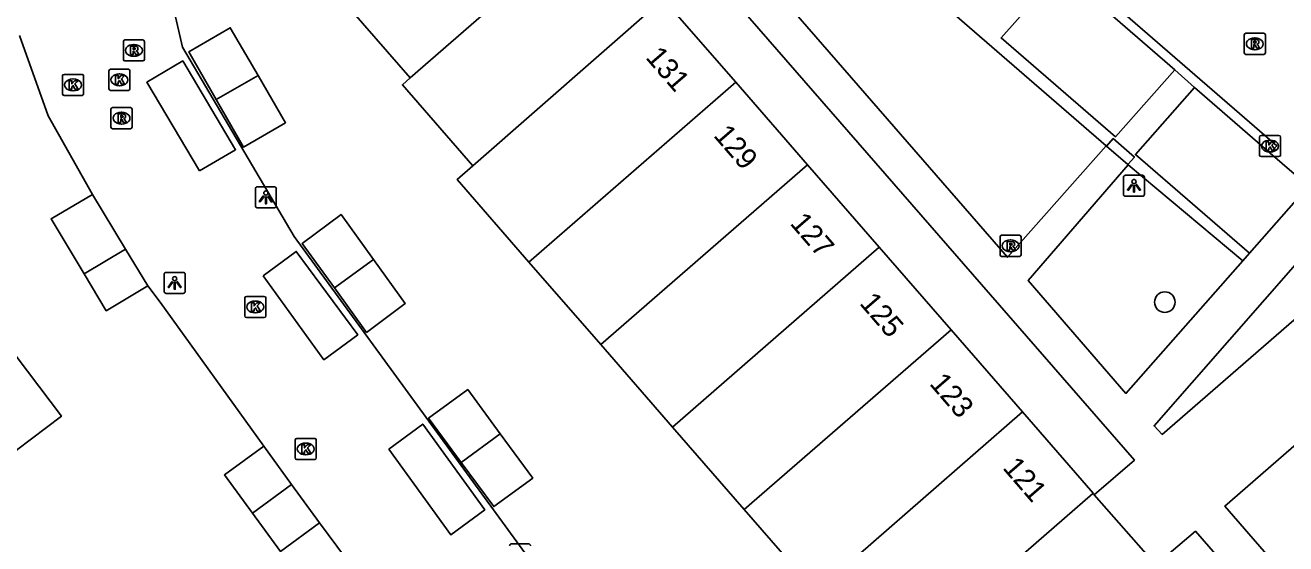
# Model space of a CAD drawing. Extents: x 161882 to 162509, y 381687 to 382379.
# Drawn here: x 161977.5 to 162037.4, y 382136.1 to 382160.8 of the extents above; entities that cross this region are included whole.
import ezdxf

# ---------------------------------------------------------------- set-up
doc = ezdxf.new("R2010")
doc.units = 0
for name, color, linetype in [('IMGEO_Boom', 7, 'Continuous'), ('IMGEO_Kolk', 7, 'Continuous'), ('IMGEO_Lichtpunt', 7, 'Continuous'), ('IMGEO_Pand', 7, 'Continuous'), ('IMGEO_Pand_nummerreeks', 7, 'Continuous'), ('IMGEO_Rijbaan_lokaal_open', 7, 'Continuous'), ('IMGEO_Rioolput', 7, 'Continuous'), ('IMGEO_Voetpad_open', 7, 'Continuous')]:
    doc.layers.add(name, color=color, linetype=linetype)

msp = doc.modelspace()

# ---------------------------------------------------------------- linework, layer by layer
at = {"layer": 'IMGEO_Boom'}
msp.add_circle((162031.641, 382147.613), 0.489, dxfattribs=at)
at = {"layer": 'IMGEO_Kolk'}
for p, q in [((161981.575, 382158.667), (161982.427, 382158.667)), ((161979.297, 382157.502), (161979.297, 382158.354)), ((161979.372, 382158.428), (161980.224, 382158.428)), ((161979.785, 382158.208), (161979.81, 382158.208)), ((161980.298, 382158.354), (161980.298, 382157.502)), ((161981.5, 382157.741), (161981.5, 382158.593)), ((161981.988, 382158.447), (161982.013, 382158.447)), ((161982.501, 382158.593), (161982.501, 382157.741)), ((161980.224, 382157.428), (161979.372, 382157.428)), ((161979.808, 382157.648), (161979.783, 382157.648)), ((161982.427, 382157.667), (161981.575, 382157.667)), ((161982.011, 382157.887), (161981.986, 382157.887)), ((162036.135, 382154.598), (162036.135, 382155.45)), ((162036.21, 382155.524), (162037.062, 382155.524)), ((162036.623, 382155.304), (162036.648, 382155.304)), ((162037.136, 382155.45), (162037.136, 382154.598)), ((162037.062, 382154.524), (162036.21, 382154.524)), ((162036.646, 382154.744), (162036.621, 382154.744)), ((161988.027, 382147.885), (161988.879, 382147.885)), ((161987.952, 382146.959), (161987.952, 382147.811)), ((161988.44, 382147.665), (161988.465, 382147.665)), ((161988.953, 382147.811), (161988.953, 382146.959)), ((161988.879, 382146.885), (161988.027, 382146.885)), ((161988.463, 382147.105), (161988.438, 382147.105)), ((161990.347, 382140.216), (161990.347, 382141.068)), ((161990.422, 382141.142), (161991.274, 382141.142)), ((161990.835, 382140.922), (161990.86, 382140.922)), ((161991.348, 382141.068), (161991.348, 382140.216)), ((161991.274, 382140.142), (161990.422, 382140.142)), ((161990.858, 382140.362), (161990.833, 382140.362))]:
    msp.add_line(p, q, dxfattribs=at)
for points in [[(161981.575, 382158.667), (161982.427, 382158.667)], [(161979.297, 382157.502), (161979.297, 382158.354)], [(161979.372, 382158.428), (161980.224, 382158.428)], [(161979.618, 382158.128), (161979.741, 382158.128), (161979.741, 382157.977), (161979.871, 382158.128), (161980.035, 382158.128), (161979.889, 382157.977), (161980.042, 382157.728), (161979.89, 382157.728), (161979.805, 382157.892), (161979.741, 382157.825), (161979.741, 382157.728), (161979.618, 382157.728), (161979.618, 382158.128)], [(161980.298, 382158.354), (161980.298, 382157.502)], [(161981.5, 382157.741), (161981.5, 382158.593)], [(161981.821, 382158.367), (161981.944, 382158.367), (161981.944, 382158.216), (161982.074, 382158.367), (161982.238, 382158.367), (161982.092, 382158.216), (161982.245, 382157.967), (161982.093, 382157.967), (161982.008, 382158.131), (161981.944, 382158.064), (161981.944, 382157.967), (161981.821, 382157.967), (161981.821, 382158.367)], [(161982.501, 382158.593), (161982.501, 382157.741)], [(161980.224, 382157.428), (161979.372, 382157.428)], [(161982.427, 382157.667), (161981.575, 382157.667)], [(162036.135, 382154.598), (162036.135, 382155.45)], [(162036.21, 382155.524), (162037.062, 382155.524)], [(162036.456, 382155.224), (162036.579, 382155.224), (162036.579, 382155.073), (162036.709, 382155.224), (162036.873, 382155.224), (162036.727, 382155.073), (162036.88, 382154.824), (162036.728, 382154.824), (162036.643, 382154.988), (162036.579, 382154.921), (162036.579, 382154.824), (162036.456, 382154.824), (162036.456, 382155.224)], [(162037.136, 382155.45), (162037.136, 382154.598)], [(162037.062, 382154.524), (162036.21, 382154.524)], [(161988.027, 382147.885), (161988.879, 382147.885)], [(161987.952, 382146.959), (161987.952, 382147.811)], [(161988.273, 382147.585), (161988.396, 382147.585), (161988.396, 382147.434), (161988.526, 382147.585), (161988.69, 382147.585), (161988.544, 382147.434), (161988.697, 382147.185), (161988.545, 382147.185), (161988.46, 382147.349), (161988.396, 382147.282), (161988.396, 382147.185), (161988.273, 382147.185), (161988.273, 382147.585)], [(161988.953, 382147.811), (161988.953, 382146.959)], [(161988.879, 382146.885), (161988.027, 382146.885)], [(161990.347, 382140.216), (161990.347, 382141.068)], [(161990.422, 382141.142), (161991.274, 382141.142)], [(161990.668, 382140.842), (161990.791, 382140.842), (161990.791, 382140.691), (161990.921, 382140.842), (161991.085, 382140.842), (161990.939, 382140.691), (161991.092, 382140.442), (161990.94, 382140.442), (161990.855, 382140.606), (161990.791, 382140.539), (161990.791, 382140.442), (161990.668, 382140.442), (161990.668, 382140.842)], [(161991.348, 382141.068), (161991.348, 382140.216)], [(161991.274, 382140.142), (161990.422, 382140.142)]]:
    msp.add_lwpolyline(points, dxfattribs=at)
for centre, start, end in [((161981.577, 382158.591), 91.55205, 178.44795), ((161981.577, 382158.591), 91.55205, 178.44795), ((161982.425, 382158.591), 1.55205, 88.44795), ((161982.425, 382158.591), 1.55205, 88.44795), ((161979.374, 382158.352), 91.55205, 178.44795), ((161979.374, 382158.352), 91.55205, 178.44795), ((161980.222, 382158.352), 1.55205, 88.44795), ((161980.222, 382158.352), 1.55205, 88.44795), ((161979.374, 382157.504), 181.55205, 268.44795), ((161979.374, 382157.504), 181.55205, 268.44795), ((161980.222, 382157.504), 271.55205, 358.44795), ((161980.222, 382157.504), 271.55205, 358.44795), ((161981.577, 382157.743), 181.55205, 268.44795), ((161981.577, 382157.743), 181.55205, 268.44795), ((161982.425, 382157.743), 271.55205, 358.44795), ((161982.425, 382157.743), 271.55205, 358.44795), ((162036.212, 382155.448), 91.55205, 178.44795), ((162036.212, 382155.448), 91.55205, 178.44795), ((162037.06, 382155.448), 1.55205, 88.44795), ((162037.06, 382155.448), 1.55205, 88.44795), ((162036.212, 382154.6), 181.55205, 268.44795), ((162036.212, 382154.6), 181.55205, 268.44795), ((162037.06, 382154.6), 271.55205, 358.44795), ((162037.06, 382154.6), 271.55205, 358.44795), ((161988.029, 382147.809), 91.55205, 178.44795), ((161988.029, 382147.809), 91.55205, 178.44795), ((161988.877, 382147.809), 1.55205, 88.44795), ((161988.877, 382147.809), 1.55205, 88.44795), ((161988.029, 382146.961), 181.55205, 268.44795), ((161988.029, 382146.961), 181.55205, 268.44795), ((161988.877, 382146.961), 271.55205, 358.44795), ((161988.877, 382146.961), 271.55205, 358.44795), ((161990.424, 382141.066), 91.55205, 178.44795), ((161990.424, 382141.066), 91.55205, 178.44795), ((161991.272, 382141.066), 1.55205, 88.44795), ((161991.272, 382141.066), 1.55205, 88.44795), ((161990.424, 382140.218), 181.55205, 268.44795), ((161990.424, 382140.218), 181.55205, 268.44795), ((161991.272, 382140.218), 271.55205, 358.44795), ((161991.272, 382140.218), 271.55205, 358.44795)]:
    msp.add_arc(centre, 0.0765, start, end, dxfattribs=at)
for centre, major_axis, ratio, start_param, end_param in [((161979.784, 382157.928), (-0.387, 0.002), 0.722429, 4.712389, 7.853982), ((161979.809, 382157.928), (-0.39, 0.002), 0.717154, 1.570796, 4.712389), ((161981.987, 382158.167), (-0.387, 0.002), 0.722429, 4.712389, 7.853982), ((161982.012, 382158.167), (-0.39, 0.002), 0.717154, 1.570796, 4.712389), ((162036.622, 382155.024), (-0.387, 0.002), 0.722429, 4.712389, 7.853982), ((162036.647, 382155.024), (-0.39, 0.002), 0.717154, 1.570796, 4.712389), ((161988.439, 382147.385), (-0.387, 0.002), 0.722429, 4.712389, 7.853982), ((161988.464, 382147.385), (-0.39, 0.002), 0.717154, 1.570796, 4.712389), ((161990.834, 382140.642), (-0.387, 0.002), 0.722429, 4.712389, 7.853982), ((161990.859, 382140.642), (-0.39, 0.002), 0.717154, 1.570796, 4.712389)]:
    msp.add_ellipse(centre, major_axis=major_axis, ratio=ratio, start_param=start_param, end_param=end_param, dxfattribs=at)
at = {"layer": 'IMGEO_Lichtpunt'}
for p, q in [((162029.678, 382153.541), (162029.678, 382152.734)), ((162029.678, 382153.541), (162029.678, 382152.734)), ((162030.58, 382153.636), (162029.772, 382153.636)), ((162030.58, 382153.636), (162029.772, 382153.636)), ((162030.674, 382152.734), (162030.674, 382153.541)), ((162030.674, 382152.734), (162030.674, 382153.541)), ((161988.455, 382152.994), (161988.455, 382152.187)), ((161988.455, 382152.994), (161988.455, 382152.187)), ((161989.357, 382153.089), (161988.549, 382153.089)), ((161989.357, 382153.089), (161988.549, 382153.089)), ((161989.451, 382152.187), (161989.451, 382152.994)), ((161989.451, 382152.187), (161989.451, 382152.994)), ((162029.772, 382152.64), (162030.58, 382152.64)), ((162029.772, 382152.64), (162030.58, 382152.64)), ((161988.549, 382152.093), (161989.357, 382152.093)), ((161988.549, 382152.093), (161989.357, 382152.093)), ((161984.126, 382148.93), (161984.126, 382148.123)), ((161984.126, 382148.93), (161984.126, 382148.123)), ((161985.028, 382149.025), (161984.22, 382149.025)), ((161985.028, 382149.025), (161984.22, 382149.025)), ((161985.122, 382148.123), (161985.122, 382148.93)), ((161985.122, 382148.123), (161985.122, 382148.93)), ((161984.22, 382148.029), (161985.028, 382148.029)), ((161984.22, 382148.029), (161985.028, 382148.029)), ((162001.427, 382136.14), (162000.619, 382136.14)), ((162001.427, 382136.14), (162000.619, 382136.14))]:
    msp.add_line(p, q, dxfattribs=at)
for points in [[(161988.829, 382152.658), (161988.868, 382152.63), (161988.68, 382152.368), (161988.642, 382152.395), (161988.829, 382152.658)], [(161989.041, 382152.63), (161989.079, 382152.657), (161989.266, 382152.395), (161989.227, 382152.367), (161989.041, 382152.63)], [(162030.052, 382153.205), (162030.091, 382153.177), (162029.903, 382152.915), (162029.865, 382152.942), (162030.052, 382153.205)], [(162030.154, 382153.157), (162030.201, 382153.157), (162030.201, 382152.835), (162030.154, 382152.835), (162030.154, 382153.157)], [(162030.264, 382153.177), (162030.302, 382153.204), (162030.489, 382152.942), (162030.45, 382152.914), (162030.264, 382153.177)], [(161988.931, 382152.61), (161988.978, 382152.61), (161988.978, 382152.288), (161988.931, 382152.288), (161988.931, 382152.61)], [(161984.5, 382148.594), (161984.539, 382148.566), (161984.351, 382148.304), (161984.313, 382148.331), (161984.5, 382148.594)], [(161984.602, 382148.546), (161984.649, 382148.546), (161984.649, 382148.224), (161984.602, 382148.224), (161984.602, 382148.546)], [(161984.712, 382148.566), (161984.75, 382148.593), (161984.937, 382148.331), (161984.898, 382148.303), (161984.712, 382148.566)]]:
    msp.add_lwpolyline(points, dxfattribs=at)
for centre in [(162030.177, 382153.339), (161988.954, 382152.792), (161984.625, 382148.728)]:
    msp.add_circle(centre, 0.0994, dxfattribs=at)
for centre, start, end in [((162029.772, 382153.541), 90, 180), ((162029.772, 382153.541), 90, 180), ((162030.58, 382153.541), 0, 90), ((162030.58, 382153.541), 0, 90), ((161988.549, 382152.994), 90, 180), ((161988.549, 382152.994), 90, 180), ((161989.357, 382152.994), 0, 90), ((161989.357, 382152.994), 0, 90), ((162029.772, 382152.734), 180, 270), ((162029.772, 382152.734), 180, 270), ((162030.58, 382152.734), 270, 0), ((162030.58, 382152.734), 270, 360), ((161988.549, 382152.187), 180, 270), ((161988.549, 382152.187), 180, 270), ((161989.357, 382152.187), 270, 0), ((161989.357, 382152.187), 270, 360), ((161984.22, 382148.93), 90, 180), ((161984.22, 382148.93), 90, 180), ((161985.028, 382148.93), 0, 90), ((161985.028, 382148.93), 0, 90), ((161984.22, 382148.123), 180, 270), ((161984.22, 382148.123), 180, 270), ((161985.028, 382148.123), 270, 0), ((161985.028, 382148.123), 270, 360), ((162000.619, 382136.045), 90, 180), ((162000.619, 382136.045), 90, 180), ((162001.427, 382136.045), 0, 90), ((162001.427, 382136.045), 0, 90)]:
    msp.add_arc(centre, 0.0946, start, end, dxfattribs=at)
at = {"layer": 'IMGEO_Pand'}
for points in [[(161995.812, 382158.259), (162004.5, 382165.829)], [(161995.812, 382158.259), (161992.464, 382162.114), (161993.025, 382162.6)], [(162007.819, 382162.014), (161998.778, 382154.082)], [(162007.819, 382162.014), (162011.263, 382158.057)], [(161986.59, 382157.233), (161985.29, 382159.491), (161987.263, 382160.644), (161988.581, 382158.38)], [(161988.581, 382158.38), (161989.893, 382156.127), (161987.89, 382154.975), (161986.59, 382157.233)], [(161986.59, 382157.233), (161988.581, 382158.38)], [(161998.778, 382154.082), (161995.439, 382157.934), (161995.812, 382158.259)], [(162011.263, 382158.057), (162001.445, 382149.514)], [(162011.263, 382158.057), (162014.672, 382154.139)], [(162001.445, 382149.514), (161998.036, 382153.431), (161998.778, 382154.082)], [(162004.853, 382145.596), (162014.672, 382154.139)], [(162014.672, 382154.139), (162018.08, 382150.222)], [(161980.324, 382148.955), (161978.753, 382151.575), (161980.726, 382152.72)], [(161980.726, 382152.72), (161982.291, 382150.133)], [(161992.21, 382148.289), (161990.682, 382150.401), (161992.528, 382151.781), (161994.072, 382149.636)], [(161982.291, 382150.133), (161980.324, 382148.955)], [(161982.291, 382150.133), (161983.351, 382148.38)], [(161994.072, 382149.636), (161995.572, 382147.554), (161993.738, 382146.177), (161992.21, 382148.289)], [(161992.21, 382148.289), (161994.072, 382149.636)], [(162018.08, 382150.222), (162008.262, 382141.679)], [(162018.08, 382150.222), (162021.489, 382146.305)], [(162004.853, 382145.596), (162001.445, 382149.514)], [(161983.351, 382148.38), (161981.375, 382147.201), (161980.324, 382148.955)], [(162021.489, 382146.305), (162011.67, 382137.761)], [(162021.489, 382146.305), (162024.884, 382142.404)], [(162008.262, 382141.679), (162004.853, 382145.596)], [(161965.061, 382130.908), (161972.501, 382136.553), (161972.827, 382136.122), (161974.839, 382137.64), (161974.538, 382138.04), (161976.878, 382139.805), (161977.107, 382140.581), (161979.246, 382142.194), (161977.09, 382145.052), (161970.383, 382139.994)], [(161998.232, 382140.005), (161996.684, 382142.103), (161998.537, 382143.459), (162000.079, 382141.367)], [(162024.884, 382142.404), (162015.457, 382134.174)], [(162024.884, 382142.404), (162028.242, 382138.545), (162028.227, 382138.532)], [(162000.079, 382141.367), (162001.631, 382139.261), (161999.779, 382137.907), (161998.232, 382140.005)], [(161998.232, 382140.005), (162000.079, 382141.367)], [(162011.67, 382137.761), (162008.262, 382141.679)], [(161988.317, 382137.593), (161986.986, 382139.41), (161988.85, 382140.776)], [(161988.85, 382140.776), (161990.178, 382138.957)], [(161990.178, 382138.957), (161988.317, 382137.593)], [(161990.178, 382138.957), (161991.508, 382137.137)], [(162018.798, 382130.333), (162028.227, 382138.532)], [(162015.457, 382134.174), (162015.079, 382133.844), (162011.67, 382137.761)], [(161991.508, 382137.137), (161989.649, 382135.775), (161988.317, 382137.593)]]:
    msp.add_lwpolyline(points, dxfattribs=at)
at = {"layer": 'IMGEO_Rijbaan_lokaal_open'}
for points in [[(162036.646, 382154.691), (162036.967, 382155.028), (162001.899, 382185.403), (162000.705, 382186.422), (162000.438, 382186.65), (162000.135, 382186.301)], [(162010.46, 382123.082), (161990.302, 382150.73), (161984.998, 382159.715), (161980.188, 382180.574), (161980.177, 382180.625)], [(162026.682, 382163.354), (162032.109, 382158.646)], [(161977.25, 382160.268), (161978.622, 382156.462), (161980.726, 382152.72)], [(161985.8, 382153.843), (161983.301, 382158.05), (161985.004, 382159.062), (161987.518, 382154.845), (161985.8, 382153.843)], [(162033.054, 382157.803), (162032.109, 382158.646)], [(162033.054, 382157.803), (162036.646, 382154.691)], [(162036.646, 382154.691), (162038.456, 382153.122)], [(161988.825, 382148.858), (161990.399, 382150.018), (161993.32, 382146.068), (161991.708, 382144.88), (161988.825, 382148.858)], [(161983.351, 382148.38), (161983.941, 382147.611), (161988.85, 382140.776)], [(161994.801, 382140.635), (161996.401, 382141.827), (161999.349, 382137.746), (161997.743, 382136.564), (161994.801, 382140.635)], [(161991.508, 382137.137), (161995.614, 382131.603)]]:
    msp.add_lwpolyline(points, dxfattribs=at)
at = {"layer": 'IMGEO_Rioolput'}
for p, q in [((161982.187, 382159.138), (161982.187, 382159.99)), ((161982.262, 382160.064), (161983.114, 382160.064)), ((161982.675, 382159.844), (161982.7, 382159.844)), ((161983.188, 382159.99), (161983.188, 382159.138)), ((162035.413, 382159.452), (162035.413, 382160.304)), ((162035.488, 382160.378), (162036.34, 382160.378)), ((162035.901, 382160.158), (162035.926, 382160.158)), ((162036.414, 382160.304), (162036.414, 382159.452)), ((161982.698, 382159.284), (161982.673, 382159.284)), ((162036.34, 382159.378), (162035.488, 382159.378)), ((162035.924, 382159.598), (162035.899, 382159.598)), ((161983.114, 382159.064), (161982.262, 382159.064)), ((161981.675, 382156.848), (161982.527, 382156.848)), ((161981.6, 382155.922), (161981.6, 382156.774)), ((161982.088, 382156.628), (161982.113, 382156.628)), ((161982.601, 382156.774), (161982.601, 382155.922)), ((161982.527, 382155.848), (161981.675, 382155.848)), ((161982.111, 382156.068), (161982.086, 382156.068)), ((162023.815, 382149.86), (162023.815, 382150.712)), ((162023.89, 382150.786), (162024.742, 382150.786)), ((162024.303, 382150.566), (162024.328, 382150.566)), ((162024.816, 382150.712), (162024.816, 382149.86)), ((162024.742, 382149.786), (162023.89, 382149.786)), ((162024.326, 382150.006), (162024.301, 382150.006))]:
    msp.add_line(p, q, dxfattribs=at)
for points in [[(161982.187, 382159.138), (161982.187, 382159.99)], [(161982.262, 382160.064), (161983.114, 382160.064)], [(161983.188, 382159.99), (161983.188, 382159.138)], [(162035.413, 382159.452), (162035.413, 382160.304)], [(162035.488, 382160.378), (162036.34, 382160.378)], [(162036.002, 382160.076), (162035.75, 382160.078), (162035.75, 382159.678)], [(162035.75, 382159.678), (162035.874, 382159.678), (162035.874, 382159.84), (162035.885, 382159.84)], [(162035.928, 382159.997), (162035.874, 382159.997), (162035.874, 382159.916)], [(162035.874, 382159.916), (162035.926, 382159.916)], [(162035.932, 382159.811), (162036.003, 382159.678), (162036.143, 382159.678), (162036.078, 382159.804)], [(162036.414, 382160.304), (162036.414, 382159.452)], [(161982.776, 382159.762), (161982.524, 382159.764), (161982.524, 382159.364)], [(161982.524, 382159.364), (161982.648, 382159.364), (161982.648, 382159.526), (161982.659, 382159.526)], [(161982.702, 382159.683), (161982.648, 382159.683), (161982.648, 382159.602)], [(161982.648, 382159.602), (161982.7, 382159.602)], [(161982.706, 382159.497), (161982.777, 382159.364), (161982.917, 382159.364), (161982.852, 382159.49)], [(162036.34, 382159.378), (162035.488, 382159.378)], [(161983.114, 382159.064), (161982.262, 382159.064)], [(161981.675, 382156.848), (161982.527, 382156.848)], [(161981.6, 382155.922), (161981.6, 382156.774)], [(161982.189, 382156.546), (161981.937, 382156.548), (161981.937, 382156.148)], [(161981.937, 382156.148), (161982.061, 382156.148), (161982.061, 382156.31), (161982.072, 382156.31)], [(161982.115, 382156.467), (161982.061, 382156.467), (161982.061, 382156.386)], [(161982.061, 382156.386), (161982.113, 382156.386)], [(161982.119, 382156.281), (161982.19, 382156.148), (161982.33, 382156.148), (161982.265, 382156.274)], [(161982.601, 382156.774), (161982.601, 382155.922)], [(161982.527, 382155.848), (161981.675, 382155.848)], [(162023.815, 382149.86), (162023.815, 382150.712)], [(162023.89, 382150.786), (162024.742, 382150.786)], [(162024.404, 382150.484), (162024.152, 382150.486), (162024.152, 382150.086)], [(162024.152, 382150.086), (162024.276, 382150.086), (162024.276, 382150.248), (162024.287, 382150.248)], [(162024.33, 382150.405), (162024.276, 382150.405), (162024.276, 382150.324)], [(162024.276, 382150.324), (162024.328, 382150.324)], [(162024.816, 382150.712), (162024.816, 382149.86)], [(162024.742, 382149.786), (162023.89, 382149.786)], [(162024.334, 382150.219), (162024.405, 382150.086), (162024.545, 382150.086), (162024.48, 382150.212)]]:
    msp.add_lwpolyline(points, dxfattribs=at)
for centre, radius, start, end in [((161982.264, 382159.988), 0.0765, 91.55205, 178.44795), ((161982.264, 382159.988), 0.0765, 91.55205, 178.44795), ((161983.112, 382159.988), 0.0765, 1.55205, 88.44795), ((161983.112, 382159.988), 0.0765, 1.55205, 88.44795), ((162035.49, 382160.302), 0.0765, 91.55205, 178.44795), ((162035.49, 382160.302), 0.0765, 91.55205, 178.44795), ((162035.884, 382159.787), 0.0533, 26.02933, 88.69889), ((162035.91, 382160.105), 0.19, 274.7715, 282.96867), ((162035.934, 382159.901), 0.0964, 77.00612, 93.18647), ((162035.948, 382159.958), 0.0378, 276.66336, 79.67722), ((162036.001, 382159.966), 0.109, 350.36119, 89.41601), ((162035.999, 382159.966), 0.112, 277.58423, 350.98172), ((162035.983, 382159.751), 0.108, 29.51342, 73.79051), ((162036.338, 382160.302), 0.0765, 1.55205, 88.44795), ((162036.338, 382160.302), 0.0765, 1.55205, 88.44795), ((161982.658, 382159.473), 0.0533, 26.02933, 88.69889), ((161982.684, 382159.791), 0.19, 274.7715, 282.96867), ((161982.708, 382159.587), 0.0964, 77.00612, 93.18647), ((161982.722, 382159.644), 0.0378, 276.66336, 79.67722), ((161982.775, 382159.652), 0.109, 350.36119, 89.41601), ((161982.773, 382159.652), 0.112, 277.58423, 350.98172), ((161982.757, 382159.437), 0.108, 29.51342, 73.79051), ((162035.49, 382159.454), 0.0765, 181.55205, 268.44795), ((162035.49, 382159.454), 0.0765, 181.55205, 268.44795), ((162036.338, 382159.454), 0.0765, 271.55205, 358.44795), ((162036.338, 382159.454), 0.0765, 271.55205, 358.44795), ((161982.264, 382159.14), 0.0765, 181.55205, 268.44795), ((161982.264, 382159.14), 0.0765, 181.55205, 268.44795), ((161983.112, 382159.14), 0.0765, 271.55205, 358.44795), ((161983.112, 382159.14), 0.0765, 271.55205, 358.44795), ((161981.677, 382156.772), 0.0765, 91.55205, 178.44795), ((161981.677, 382156.772), 0.0765, 91.55205, 178.44795), ((161982.525, 382156.772), 0.0765, 1.55205, 88.44795), ((161982.525, 382156.772), 0.0765, 1.55205, 88.44795), ((161982.071, 382156.257), 0.0533, 26.02933, 88.69889), ((161982.097, 382156.575), 0.19, 274.7715, 282.96867), ((161982.121, 382156.371), 0.0964, 77.00612, 93.18647), ((161982.135, 382156.428), 0.0378, 276.66336, 79.67722), ((161982.188, 382156.436), 0.109, 350.36119, 89.41601), ((161982.186, 382156.436), 0.112, 277.58423, 350.98172), ((161982.17, 382156.221), 0.108, 29.51342, 73.79051), ((161981.677, 382155.924), 0.0765, 181.55205, 268.44795), ((161981.677, 382155.924), 0.0765, 181.55205, 268.44795), ((161982.525, 382155.924), 0.0765, 271.55205, 358.44795), ((161982.525, 382155.924), 0.0765, 271.55205, 358.44795), ((162023.892, 382150.71), 0.0765, 91.55205, 178.44795), ((162023.892, 382150.71), 0.0765, 91.55205, 178.44795), ((162024.286, 382150.195), 0.0533, 26.02933, 88.69889), ((162024.312, 382150.513), 0.19, 274.7715, 282.96867), ((162024.336, 382150.309), 0.0964, 77.00612, 93.18647), ((162024.35, 382150.366), 0.0378, 276.66336, 79.67722), ((162024.403, 382150.374), 0.109, 350.36119, 89.41601), ((162024.401, 382150.374), 0.112, 277.58423, 350.98172), ((162024.385, 382150.159), 0.108, 29.51342, 73.79051), ((162024.74, 382150.71), 0.0765, 1.55205, 88.44795), ((162024.74, 382150.71), 0.0765, 1.55205, 88.44795), ((162023.892, 382149.862), 0.0765, 181.55205, 268.44795), ((162023.892, 382149.862), 0.0765, 181.55205, 268.44795), ((162024.74, 382149.862), 0.0765, 271.55205, 358.44795), ((162024.74, 382149.862), 0.0765, 271.55205, 358.44795)]:
    msp.add_arc(centre, radius, start, end, dxfattribs=at)
for centre, major_axis, ratio, start_param, end_param in [((161982.674, 382159.564), (-0.387, 0.002), 0.722429, 4.712389, 7.853982), ((161982.699, 382159.564), (-0.39, 0.002), 0.717154, 1.570796, 4.712389), ((162035.9, 382159.878), (-0.387, 0.002), 0.722429, 4.712389, 7.853982), ((162035.925, 382159.878), (-0.39, 0.002), 0.717154, 1.570796, 4.712389), ((161982.087, 382156.348), (-0.387, 0.002), 0.722429, 4.712389, 7.853982), ((161982.112, 382156.348), (-0.39, 0.002), 0.717154, 1.570796, 4.712389), ((162024.302, 382150.286), (-0.387, 0.002), 0.722429, 4.712389, 7.853982), ((162024.327, 382150.286), (-0.39, 0.002), 0.717154, 1.570796, 4.712389)]:
    msp.add_ellipse(centre, major_axis=major_axis, ratio=ratio, start_param=start_param, end_param=end_param, dxfattribs=at)
at = {"layer": 'IMGEO_Voetpad_open'}
for points in [[(162028.288, 382138.462), (162030.201, 382140.112), (161996.66, 382178.627), (161990.016, 382186.254)], [(162028.853, 382155.032), (162024.17, 382149.745), (162014.005, 382161.432), (162017.138, 382165.198)], [(162017.182, 382165.16), (162028.853, 382155.032)], [(162032.109, 382158.646), (162029.293, 382155.466), (162023.868, 382160.155), (162025.936, 382162.505)], [(162035.668, 382149.938), (162030.242, 382154.62), (162033.054, 382157.803)], [(162028.853, 382155.032), (162028.872, 382155.015)], [(162028.872, 382155.015), (162029.192, 382155.382), (162030.197, 382154.504), (162029.88, 382154.141)], [(162029.88, 382154.141), (162028.872, 382155.015)], [(162035.341, 382149.568), (162029.793, 382143.281), (162025.152, 382148.644), (162029.896, 382154.126)], [(162029.88, 382154.141), (162029.896, 382154.126)], [(162029.896, 382154.126), (162035.341, 382149.568)], [(162038.456, 382153.122), (162035.668, 382149.938)], [(162041.933, 382150.436), (162041.747, 382150.205), (162031.515, 382141.331), (162031.132, 382141.739), (162039.963, 382151.816)], [(162035.341, 382149.568), (162035.668, 382149.938)], [(162055.435, 382113.796), (162034.496, 382137.927), (162040.79, 382143.399)], [(162028.227, 382138.532), (162028.288, 382138.462)], [(162028.288, 382138.462), (162031.212, 382135.133)], [(162031.212, 382135.133), (162033.092, 382136.738), (162050.208, 382117.073), (162048.327, 382115.452)]]:
    msp.add_lwpolyline(points, dxfattribs=at)

# ---------------------------------------------------------------- texts
at = {"layer": 'IMGEO_Pand_nummerreeks'}
for s, p in [('131', (162006.947, 382159.215)), ('129', (162010.173, 382155.508)), ('127', (162013.804, 382151.336)), ('125', (162017.106, 382147.541)), ('123', (162020.428, 382143.723)), ('121', (162023.904, 382139.729))]:
    msp.add_text(s, height=1, rotation=310.83449, dxfattribs=at).set_placement(p)

doc.saveas('drawing.dxf')
